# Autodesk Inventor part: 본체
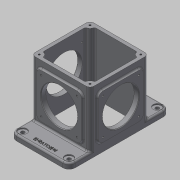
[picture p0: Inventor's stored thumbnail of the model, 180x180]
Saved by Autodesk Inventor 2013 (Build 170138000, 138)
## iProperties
Created: 2018-09
Part Number: 본체
Material: 알루미늄 6061
Document SubType Name: Modeling
Designer: mduedu
Density: 1 g/cm^3
Author: mduedu
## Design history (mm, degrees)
sketch "스케치1"
  geometry: L1 (90, 52.5)-(-90, 52.5); L2 (-90, 52.5)-(-90, -52.5); L3 (-90, -52.5)-(90, -52.5); L4 (90, -52.5)-(90, 52.5); L5 (90, 52.5)-(-90, -52.5); L6 (-90, 52.5)-(90, -52.5); 1 further point
  constraints: 12 end point, 2 midpoint, 2 parallel, 1 horizontal, 1 perpendicular
  dimensions: "d0" = 180 distance of L3.end L2.end; "d1" = 105 distance of L2.end L1.end
extrude "돌출1" new body sketch "스케치1" distance "d2" = 10; taper "d3" = 0 deg
sketch "스케치2"
  geometry: L1 (-52.5, -52.5)-(52.5, -52.5); L2 (52.5, -52.5)-(52.5, 52.5); L3 (52.5, 52.5)-(-52.5, 52.5); L4 (-52.5, 52.5)-(-52.5, -52.5); L5 (-52.5, -52.5)-(52.5, 52.5); L6 (52.5, -52.5)-(-52.5, 52.5); 1 further point
  constraints: 12 end point, 2 midpoint, 2 parallel, 1 horizontal, 1 perpendicular
  dimensions: "d4" = 105 distance of L3.end L2.end; "d5" = 105 distance of L2.end L1.end
extrude "돌출2" join sketch "스케치2" distance "d6" = 100; taper "d7" = 0 deg
sketch "스케치14"
  geometry: L1 (-52.5, 52.5)-(52.5, 52.5) reference; L2 (52.5, 52.5)-(52.5, -52.5) reference; L3 (52.5, -52.5)-(-52.5, -52.5) reference; L4 (-52.5, -52.5)-(-52.5, 52.5) reference; L5 (46.5, 46.5)-(-46.5, 46.5); L6 (-46.5, 46.5)-(-46.5, -46.5); L7 (-46.5, -46.5)-(46.5, -46.5); L8 (46.5, -46.5)-(46.5, 46.5); 1 further point
  constraints: 8 end point, 3 other
  dimensions: "d85" = 6 distance between parallel lines of L5 L1
extrude "돌출10" cut sketch "스케치14" stored distance "d86" = 10; taper "d87" = 0 deg
fillet "모깎기1" dims "d12" = 7
sketch "스케치15"
  geometry: A1 r 7 centre (-45.5, 45.5) between (-45.5, 52.5) and (-52.5, 45.5) reference; A2 r 7 centre (45.5, 45.5) between (52.5, 45.5) and (45.5, 52.5) reference; A3 r 7 centre (45.5, -45.5) between (45.5, -52.5) and (52.5, -45.5) reference; A4 r 7 centre (-45.5, -45.5) between (-52.5, -45.5) and (-45.5, -52.5) reference; 5 further points
  constraints: 4 coincident, 4 vertical alignment, 8 other
extrude "돌출11" join sketch "스케치15" stored distance "d88" = 10; taper "d89" = 0 deg
fillet "모깎기15" dims "d90" = 3
sketch "스케치6"
  geometry: L1 (50, 17.5)-(130, 17.5); L2 (130, 17.5)-(130, 97.5); L3 (130, 97.5)-(50, 97.5); L4 (50, 97.5)-(50, 17.5); L5 (50, 17.5)-(130, 97.5); L6 (130, 17.5)-(50, 97.5); L7 (0, 0)-(180, 0) reference; 4 further points
  constraints: 12 end point, 4 midpoint, 2 parallel, 1 horizontal, 1 perpendicular, 1 vertical alignment
  dimensions: "d25" = 80 distance of L3.end L2.end; "d26" = 80 distance of L2.end L1.end; "d27" = 57.5 distance of point (90, 0) point (90, 57.5)
extrude "돌출6" join sketch "스케치6" distance "d28" = 3; taper "d29" = 0 deg
fillet "모깎기7" dims "d30" = 8
sketch "스케치7"
  geometry: C1 r 32.5 at (90, 57.5); 1 further point
  constraints: 1 centre point, 1 vertical alignment
  dimensions: "d32" = 65 diameter of C1; "d33" = 57.5 distance of C1.centre point (90, 0)
extrude "돌출7" cut sketch "스케치7" stored distance "d34" = 3; taper "d35" = 0 deg
fillet "모깎기9" dims "d36" = 3
sketch "스케치8"
  geometry: L1 (5.5, 7.5)-(85.5, 7.5); L2 (85.5, 7.5)-(85.5, 87.5); L3 (85.5, 87.5)-(5.5, 87.5); L4 (5.5, 87.5)-(5.5, 7.5); L5 (5.5, 7.5)-(85.5, 87.5); L6 (85.5, 7.5)-(5.5, 87.5); L7 (-7, -10)-(98, -10) reference; C1 r 32.5 at (45.5, 47.5); 4 further points
  constraints: 12 end point, 4 midpoint, 2 parallel, 1 centre point, 1 coincident, 1 horizontal, 1 perpendicular, 1 vertical alignment
  dimensions: "d37" = 80 distance of L3.end L2.end; "d38" = 80 distance of L2.end L1.end; "d39" = 57.5 distance from line of point (45.5, 47.5) L7; "d40" = 65 diameter of C1
extrude "돌출8" join sketch "스케치8" distance "d41" = 3; taper "d42" = 0 deg
fillet "모깎기10" dims "d43" = 8
extrude "돌출9" cut sketch "스케치8" stored distance "d44" = 3; taper "d45" = 0 deg
fillet "모깎기11" dims "d46" = 3
sketch "스케치9"
  geometry: L1 (50, 89.5)-(50, 25.5) reference; L2 (58, 17.5)-(122, 17.5) reference; L3 (130, 25.5)-(130, 89.5) reference; L4 (122, 97.5)-(58, 97.5) reference; C1 r 32.5 at (90, 57.5) reference; A1 r 8 centre (58, 89.5) between (58, 97.5) and (50, 89.5) reference; A2 r 8 centre (58, 25.5) between (50, 25.5) and (58, 17.5) reference; A3 r 8 centre (122, 25.5) between (122, 17.5) and (130, 25.5) reference; A4 r 8 centre (122, 89.5) between (130, 89.5) and (122, 97.5) reference; 5 further points
  constraints: 4 coincident
hole "구멍1" sketch "스케치9" at (58, 89.5), (122, 89.5), (122, 25.5), (58, 25.5) diameter "d47" = 3.242; stored, may be unused: countersink angle "d51" = 90 deg, drill point angle "d53" = 118 deg; dims "d48" = 6, "d49" = 4, "d50" = 2, "d52" = 9
sketch "스케치10" dims "d30" = 8
  geometry: L1 (13.5, 7.5)-(77.5, 7.5) reference; L2 (85.5, 15.5)-(85.5, 79.5) reference; L3 (77.5, 87.5)-(13.5, 87.5) reference; L4 (5.5, 79.5)-(5.5, 15.5) reference; C1 r 32.5 at (45.5, 47.5) reference; A1 r 8 centre (13.5, 15.5) between (5.5, 15.5) and (13.5, 7.5) reference; A2 r 8 centre (77.5, 15.5) between (77.5, 7.5) and (85.5, 15.5) reference; A3 r 8 centre (77.5, 79.5) between (85.5, 79.5) and (77.5, 87.5) reference; A4 r 8 centre (13.5, 79.5) between (13.5, 87.5) and (5.5, 79.5) reference; 5 further points
  constraints: 4 coincident
hole "구멍2" sketch "스케치10" at (13.5, 79.5), (77.5, 79.5), (77.5, 15.5), (13.5, 15.5) diameter "d54" = 3.242; stored, may be unused: countersink angle "d58" = 90 deg, drill point angle "d60" = 118 deg; dims "d30" = 8, "d55" = 6, "d56" = 4, "d57" = 2, "d59" = 9
fillet "모깎기12" dims "d68" = 11
sketch "스케치16"
  geometry: A1 r 11 centre (-79, 41.5) between (-79, 52.5) and (-90, 41.5) reference; A2 r 11 centre (-79, -41.5) between (-90, -41.5) and (-79, -52.5) reference; A3 r 11 centre (79, 41.5) between (90, 41.5) and (79, 52.5) reference; A4 r 11 centre (79, -41.5) between (79, -52.5) and (90, -41.5) reference; 5 further points
  constraints: 4 coincident
hole "구멍5" sketch "스케치16" at (-79, 41.5), (79, 41.5), (79, -41.5), (-79, -41.5) diameter "d91" = 6.6; stored, may be unused: countersink angle "d95" = 90 deg, drill point angle "d97" = 118 deg; dims "d92" = 6, "d93" = 15, "d94" = 2, "d96" = 8
fillet "모깎기13" dims "d77" = 3
fillet "모깎기14" dims "d78" = 3
chamfer "모따기1" distance "d79" = 1; stored, may be unused: second distance "d80" = 2, angle "d81" = 45 deg
sketch "스케치17"
  geometry: A1 r 7 centre (-45.5, 45.5) between (-45.5, 52.5) and (-52.5, 45.5) reference; A2 r 7 centre (-45.5, -45.5) between (-52.5, -45.5) and (-45.5, -52.5) reference; A3 r 7 centre (45.5, -45.5) between (45.5, -52.5) and (52.5, -45.5) reference; A4 r 7 centre (45.5, 45.5) between (52.5, 45.5) and (45.5, 52.5) reference; 5 further points
  constraints: 4 coincident
hole "구멍6" sketch "스케치17" at (-45.5, 45.5), (45.5, 45.5), (45.5, -45.5), (-45.5, -45.5) diameter "d98" = 3.242; stored, may be unused: countersink angle "d102" = 90 deg, drill point angle "d104" = 118 deg; dims "d99" = 8, "d100" = 15, "d101" = 2, "d103" = 10
sketch "스케치13"
  geometry: L1 (90, -41.5)-(90, 41.5) reference; 2 further points
  constraints: 1 horizontal alignment, 1 other
  dimensions: "d82" = 10 distance from line of point (80, 0) L1
feature "엠보싱1" sketch "스케치13" dims "d0" = 180, "d1" = 105, "d25" = 80, "d26" = 80, "d27" = 57.5, "d83" = 0.5, "d84" = 0
node "솔리드1"
mirror "대칭1"
mirror "대칭2"
node "투영된 루프2"
node "투영된 루프3"
node "투영된 루프6"
